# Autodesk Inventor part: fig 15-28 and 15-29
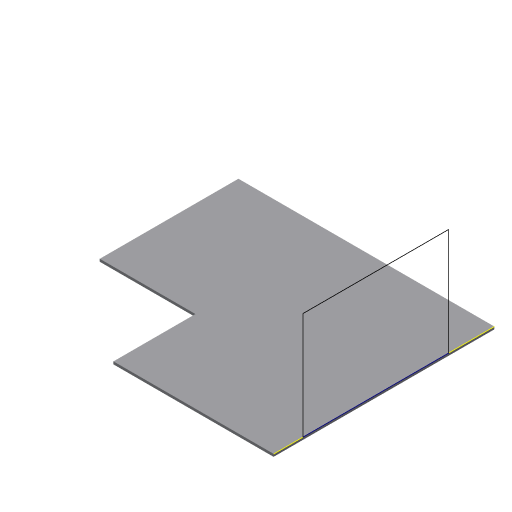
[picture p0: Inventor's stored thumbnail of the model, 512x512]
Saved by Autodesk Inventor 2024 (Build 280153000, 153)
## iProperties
Created: 2005-03
Part Number: fig 15-28 and 15-29
Document SubType Name: Sheet Metal
Designer: CADCIM
Manufacturer: Standard
Standards Organization: Custom
Density: 1 g/cm^3
Sheet Metal Rule: Default
Material: Generic
Appearance: Default
Author: CADCIM
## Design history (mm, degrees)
node "Face1"
  sketch "Sketch1"
    geometry: L1 (29.25, 32.25)-(-19.875, 32.25); L2 (-19.875, 32.25)-(-19.875, 5.625); L3 (-19.875, 5.625)-(-1.5, 5.625); L4 (-1.5, 5.625)-(-1.5, -10.125); L5 (-1.5, -10.125)-(29.25, -10.125); L6 (29.25, -10.125)-(29.25, 32.25)
    constraints: 12 end point, 4 parallel, 1 horizontal, 1 perpendicular
sketch "Sketch2"
  geometry: L1 (-0.5, 42.375)-(-0.5, 0) reference; L2 (-0.5, 5.593)-(-21.049, 5.593); L3 (-21.049, 5.593)-(-21.049, 33.56); L4 (-21.049, 33.56)-(-0.5, 33.56); L5 (-0.5, 33.56)-(-0.5, 5.593)
  constraints: 8 end point, 2 parallel, 1 horizontal, 1 perpendicular, 1 point on line
body "Solid1"
face "Plate1" dims "d1" = 0.5 (= Thickness)
other parameters: "Thickness" = 0.5, "BendRadius" = 0.5 (= Thickness), "BendReliefWidth" = 0.5 (= Thickness), "BendReliefDepth" = 0.25 (= 0.5 x Thickness), "CornerReliefSize" = 2 (= 4 x Thickness), "SeamGap" = 0.01, "MinimumRemnant" = 1 (= 2 x Thickness), "TransitionRadius" = 0.5 (= BendRadius), "d0" = 0.5 (= BendRadius), "JacobiRadiusSize" = 0.5 (= Thickness), "GapSize" = 0.5 (= Thickness)
